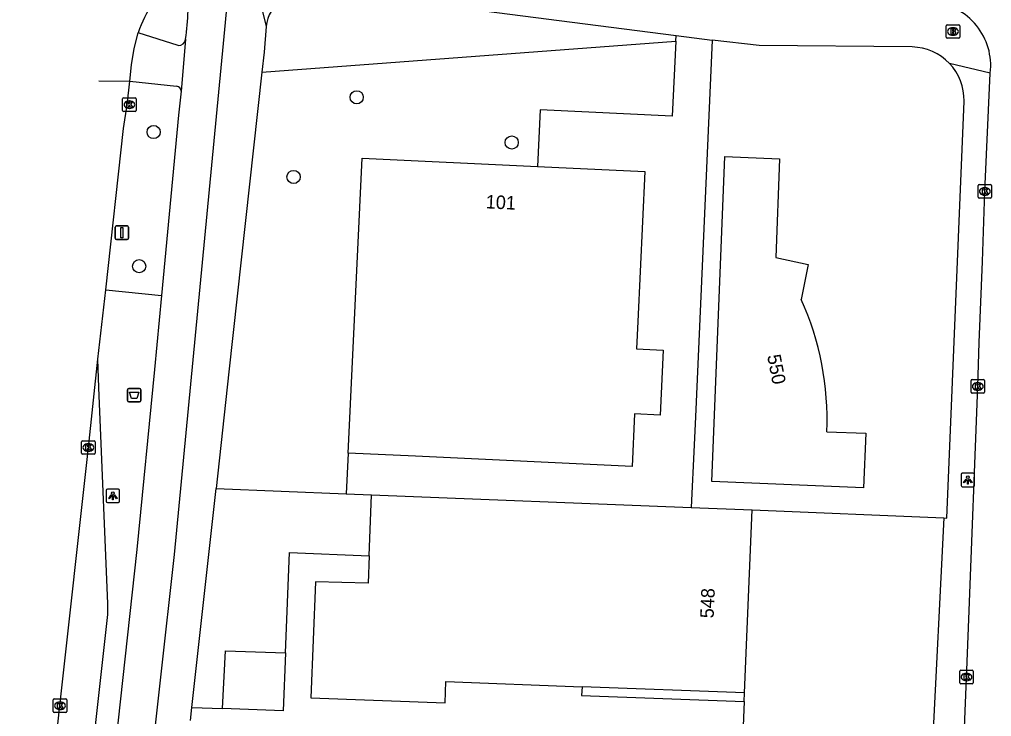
# Model space of a CAD drawing. Extents: x 161355 to 162026, y 386504 to 387459.
# Drawn here: x 161378.2 to 161450.2, y 386765.3 to 386816.9 of the extents above; entities that cross this region are included whole.
import ezdxf

# ---------------------------------------------------------------- set-up
doc = ezdxf.new("R2010")
doc.units = 0
for name, color, linetype in [('IMGEO_Afvalbak', 7, 'Continuous'), ('IMGEO_Boom', 7, 'Continuous'), ('IMGEO_Brandkraan', 7, 'Continuous'), ('IMGEO_Fietspad_gesloten', 7, 'Continuous'), ('IMGEO_Groenvoorziening', 7, 'Continuous'), ('IMGEO_Kolk', 7, 'Continuous'), ('IMGEO_Lichtpunt', 7, 'Continuous'), ('IMGEO_Pand', 7, 'Continuous'), ('IMGEO_Pand_nummerreeks', 7, 'Continuous'), ('IMGEO_Parkeervlak_open', 7, 'Continuous'), ('IMGEO_Rijbaan_lokaal_gesloten', 7, 'Continuous'), ('IMGEO_Rijbaan_lokaal_open', 7, 'Continuous'), ('IMGEO_Verkeersbordpaal', 7, 'Continuous'), ('IMGEO_Voetpad_open', 7, 'Continuous')]:
    doc.layers.add(name, color=color, linetype=linetype)

msp = doc.modelspace()

# ---------------------------------------------------------------- linework, layer by layer
at = {"layer": 'IMGEO_Afvalbak'}
for p, q in [((161386.165, 386788.673), (161386.165, 386789.473)), ((161386.165, 386789.473), (161386.165, 386788.673)), ((161386.265, 386789.573), (161387.055, 386789.573)), ((161387.055, 386789.573), (161386.265, 386789.573)), ((161387.155, 386789.473), (161387.155, 386788.673)), ((161387.155, 386788.673), (161387.155, 386789.473)), ((161387.055, 386788.573), (161386.265, 386788.573)), ((161386.265, 386788.573), (161387.055, 386788.573))]:
    msp.add_line(p, q, dxfattribs=at)
msp.add_lwpolyline([(161386.308, 386789.287), (161387.012, 386789.287), (161386.863, 386788.817), (161386.457, 386788.817), (161386.308, 386789.287)], dxfattribs=at)
for centre, start, end in [((161386.265, 386789.473), 90, 180), ((161386.265, 386789.473), 90, 180), ((161387.055, 386789.473), 0, 90), ((161387.055, 386789.473), 360, 90), ((161386.265, 386788.673), 180, 270), ((161386.265, 386788.673), 180, 270), ((161387.055, 386788.673), 270, 0), ((161387.055, 386788.673), 270, 0)]:
    msp.add_arc(centre, 0.1, start, end, dxfattribs=at)
at = {"layer": 'IMGEO_Boom'}
for centre in [(161403.147, 386811.141), (161388.097, 386808.566), (161414.628, 386807.791), (161398.469, 386805.238), (161387.028, 386798.624)]:
    msp.add_circle(centre, 0.489, dxfattribs=at)
at = {"layer": 'IMGEO_Brandkraan'}
for p, q in [((161446.822, 386815.585), (161446.822, 386816.437)), ((161446.897, 386816.511), (161447.749, 386816.511)), ((161447.31, 386816.291), (161447.335, 386816.291)), ((161447.823, 386816.437), (161447.823, 386815.585)), ((161447.749, 386815.511), (161446.897, 386815.511)), ((161447.333, 386815.731), (161447.308, 386815.731))]:
    msp.add_line(p, q, dxfattribs=at)
for points in [[(161446.822, 386815.585), (161446.822, 386816.437)], [(161446.897, 386816.511), (161447.749, 386816.511)], [(161447.17, 386816.211), (161447.17, 386815.811), (161447.383, 386815.811)], [(161447.401, 386816.211), (161447.17, 386816.211)], [(161447.349, 386816.13), (161447.295, 386816.13), (161447.295, 386816.054)], [(161447.295, 386816.054), (161447.348, 386816.054)], [(161447.357, 386815.978), (161447.295, 386815.978), (161447.295, 386815.897)], [(161447.295, 386815.897), (161447.357, 386815.897)], [(161447.823, 386816.437), (161447.823, 386815.585)], [(161447.749, 386815.511), (161446.897, 386815.511)]]:
    msp.add_lwpolyline(points, dxfattribs=at)
for centre, radius, start, end in [((161446.899, 386816.435), 0.0765, 91.55205, 178.44795), ((161446.899, 386816.435), 0.0765, 91.55205, 178.44795), ((161447.35, 386816.092), 0.0379, 267.82845, 90.93552), ((161447.358, 386815.937), 0.0404, 269.87594, 90.50774), ((161447.405, 386816.066), 0.145, 59.4692, 91.53667), ((161447.43, 386816.113), 0.0922, 285.51372, 58.15012), ((161447.435, 386815.921), 0.105, 301.31148, 78.98903), ((161447.747, 386816.435), 0.0765, 1.55205, 88.44795), ((161447.747, 386816.435), 0.0765, 1.55205, 88.44795), ((161446.899, 386815.587), 0.0765, 181.55205, 268.44795), ((161446.899, 386815.587), 0.0765, 181.55205, 268.44795), ((161447.389, 386816.062), 0.251, 268.66757, 293.53466), ((161447.747, 386815.587), 0.0765, 271.55205, 358.44795), ((161447.747, 386815.587), 0.0765, 271.55205, 358.44795)]:
    msp.add_arc(centre, radius, start, end, dxfattribs=at)
for centre, major_axis, ratio, start_param, end_param in [((161447.309, 386816.011), (-0.387, 0.002), 0.722429, 4.712389, 7.853982), ((161447.334, 386816.011), (-0.39, 0.002), 0.717154, 1.570796, 4.712389)]:
    msp.add_ellipse(centre, major_axis=major_axis, ratio=ratio, start_param=start_param, end_param=end_param, dxfattribs=at)
at = {"layer": 'IMGEO_Fietspad_gesloten'}
for points in [[(161381.864, 386712.557), (161383.032, 386721.496), (161385.721, 386742.066), (161386.605, 386750), (161389.646, 386777.28), (161393.272, 386815.123), (161393.6, 386818.527)], [(161390.466, 386815.452), (161390.418, 386814.821), (161390.137, 386811.593)], [(161390.137, 386811.593), (161389.935, 386809.823), (161388.673, 386796.461)]]:
    msp.add_lwpolyline(points, dxfattribs=at)
msp.add_arc((161373.711, 386817.975), 16.944, 351.43496, 5.63796, dxfattribs=at)
at = {"layer": 'IMGEO_Groenvoorziening'}
for points in [[(161396.119, 386813), (161426.794, 386815.303)], [(161392.725, 386782.167), (161402.362, 386781.767)]]:
    msp.add_lwpolyline(points, dxfattribs=at)
at = {"layer": 'IMGEO_Kolk'}
for p, q in [((161385.803, 386810.167), (161385.803, 386811.019)), ((161385.878, 386811.093), (161386.73, 386811.093)), ((161386.291, 386810.873), (161386.316, 386810.873)), ((161386.804, 386811.019), (161386.804, 386810.167)), ((161386.73, 386810.093), (161385.878, 386810.093)), ((161386.314, 386810.313), (161386.289, 386810.313)), ((161449.184, 386803.743), (161449.184, 386804.595)), ((161449.259, 386804.669), (161450.111, 386804.669)), ((161449.672, 386804.449), (161449.697, 386804.449)), ((161450.185, 386804.595), (161450.185, 386803.743)), ((161450.111, 386803.669), (161449.259, 386803.669)), ((161449.695, 386803.889), (161449.67, 386803.889)), ((161448.663, 386789.296), (161448.663, 386790.148)), ((161448.738, 386790.222), (161449.59, 386790.222)), ((161449.151, 386790.002), (161449.176, 386790.002)), ((161449.664, 386790.148), (161449.664, 386789.296)), ((161449.59, 386789.222), (161448.738, 386789.222)), ((161449.174, 386789.442), (161449.149, 386789.442)), ((161382.763, 386784.772), (161382.763, 386785.624)), ((161382.838, 386785.698), (161383.69, 386785.698)), ((161383.764, 386785.624), (161383.764, 386784.772)), ((161383.274, 386784.918), (161383.249, 386784.918)), ((161383.251, 386785.478), (161383.276, 386785.478)), ((161383.69, 386784.698), (161382.838, 386784.698)), ((161447.828, 386767.769), (161447.828, 386768.621)), ((161447.903, 386768.695), (161448.755, 386768.695)), ((161448.316, 386768.475), (161448.341, 386768.475)), ((161448.829, 386768.621), (161448.829, 386767.769)), ((161448.755, 386767.695), (161447.903, 386767.695)), ((161448.339, 386767.915), (161448.314, 386767.915)), ((161380.657, 386765.642), (161380.657, 386766.494)), ((161380.732, 386766.568), (161381.584, 386766.568)), ((161381.145, 386766.348), (161381.17, 386766.348)), ((161381.658, 386766.494), (161381.658, 386765.642)), ((161381.584, 386765.568), (161380.732, 386765.568)), ((161381.168, 386765.788), (161381.143, 386765.788))]:
    msp.add_line(p, q, dxfattribs=at)
for points in [[(161385.803, 386810.167), (161385.803, 386811.019)], [(161385.878, 386811.093), (161386.73, 386811.093)], [(161386.804, 386811.019), (161386.804, 386810.167)], [(161386.73, 386810.093), (161385.878, 386810.093)], [(161386.124, 386810.793), (161386.247, 386810.793), (161386.247, 386810.642), (161386.377, 386810.793), (161386.541, 386810.793), (161386.395, 386810.642), (161386.548, 386810.393), (161386.396, 386810.393), (161386.311, 386810.557), (161386.247, 386810.49), (161386.247, 386810.393), (161386.124, 386810.393), (161386.124, 386810.793)], [(161449.184, 386803.743), (161449.184, 386804.595)], [(161449.259, 386804.669), (161450.111, 386804.669)], [(161449.505, 386804.369), (161449.628, 386804.369), (161449.628, 386804.218), (161449.758, 386804.369), (161449.922, 386804.369), (161449.776, 386804.218), (161449.929, 386803.969), (161449.777, 386803.969), (161449.692, 386804.133), (161449.628, 386804.066), (161449.628, 386803.969), (161449.505, 386803.969), (161449.505, 386804.369)], [(161450.185, 386804.595), (161450.185, 386803.743)], [(161450.111, 386803.669), (161449.259, 386803.669)], [(161448.663, 386789.296), (161448.663, 386790.148)], [(161448.738, 386790.222), (161449.59, 386790.222)], [(161448.984, 386789.922), (161449.107, 386789.922), (161449.107, 386789.771), (161449.237, 386789.922), (161449.401, 386789.922), (161449.255, 386789.771), (161449.408, 386789.522), (161449.256, 386789.522), (161449.171, 386789.686), (161449.107, 386789.619), (161449.107, 386789.522), (161448.984, 386789.522), (161448.984, 386789.922)], [(161449.664, 386790.148), (161449.664, 386789.296)], [(161449.59, 386789.222), (161448.738, 386789.222)], [(161382.763, 386784.772), (161382.763, 386785.624)], [(161382.838, 386785.698), (161383.69, 386785.698)], [(161383.764, 386785.624), (161383.764, 386784.772)], [(161383.084, 386785.398), (161383.207, 386785.398), (161383.207, 386785.247), (161383.337, 386785.398), (161383.501, 386785.398), (161383.355, 386785.247), (161383.508, 386784.998), (161383.356, 386784.998), (161383.271, 386785.162), (161383.207, 386785.095), (161383.207, 386784.998), (161383.084, 386784.998), (161383.084, 386785.398)], [(161383.69, 386784.698), (161382.838, 386784.698)], [(161447.828, 386767.769), (161447.828, 386768.621)], [(161447.903, 386768.695), (161448.755, 386768.695)], [(161448.149, 386768.395), (161448.272, 386768.395), (161448.272, 386768.244), (161448.402, 386768.395), (161448.566, 386768.395), (161448.42, 386768.244), (161448.573, 386767.995), (161448.421, 386767.995), (161448.336, 386768.159), (161448.272, 386768.092), (161448.272, 386767.995), (161448.149, 386767.995), (161448.149, 386768.395)], [(161448.829, 386768.621), (161448.829, 386767.769)], [(161448.755, 386767.695), (161447.903, 386767.695)], [(161380.657, 386765.642), (161380.657, 386766.494)], [(161380.732, 386766.568), (161381.584, 386766.568)], [(161380.978, 386766.268), (161381.101, 386766.268), (161381.101, 386766.117), (161381.231, 386766.268), (161381.395, 386766.268), (161381.249, 386766.117), (161381.402, 386765.868), (161381.25, 386765.868), (161381.165, 386766.032), (161381.101, 386765.965), (161381.101, 386765.868), (161380.978, 386765.868), (161380.978, 386766.268)], [(161381.658, 386766.494), (161381.658, 386765.642)], [(161381.584, 386765.568), (161380.732, 386765.568)]]:
    msp.add_lwpolyline(points, dxfattribs=at)
for centre, start, end in [((161385.88, 386811.017), 91.55205, 178.44795), ((161385.88, 386811.017), 91.55205, 178.44795), ((161386.728, 386811.017), 1.55205, 88.44795), ((161386.728, 386811.017), 1.55205, 88.44795), ((161385.88, 386810.169), 181.55205, 268.44795), ((161385.88, 386810.169), 181.55205, 268.44795), ((161386.728, 386810.169), 271.55205, 358.44795), ((161386.728, 386810.169), 271.55205, 358.44795), ((161449.261, 386804.593), 91.55205, 178.44795), ((161449.261, 386804.593), 91.55205, 178.44795), ((161450.109, 386804.593), 1.55205, 88.44795), ((161450.109, 386804.593), 1.55205, 88.44795), ((161449.261, 386803.745), 181.55205, 268.44795), ((161449.261, 386803.745), 181.55205, 268.44795), ((161450.109, 386803.745), 271.55205, 358.44795), ((161450.109, 386803.745), 271.55205, 358.44795), ((161448.74, 386790.146), 91.55205, 178.44795), ((161448.74, 386790.146), 91.55205, 178.44795), ((161449.588, 386790.146), 1.55205, 88.44795), ((161449.588, 386790.146), 1.55205, 88.44795), ((161448.74, 386789.298), 181.55205, 268.44795), ((161448.74, 386789.298), 181.55205, 268.44795), ((161449.588, 386789.298), 271.55205, 358.44795), ((161449.588, 386789.298), 271.55205, 358.44795), ((161382.84, 386785.622), 91.55205, 178.44795), ((161382.84, 386785.622), 91.55205, 178.44795), ((161383.688, 386785.622), 1.55205, 88.44795), ((161383.688, 386785.622), 1.55205, 88.44795), ((161382.84, 386784.774), 181.55205, 268.44795), ((161382.84, 386784.774), 181.55205, 268.44795), ((161383.688, 386784.774), 271.55205, 358.44795), ((161383.688, 386784.774), 271.55205, 358.44795), ((161447.905, 386768.619), 91.55205, 178.44795), ((161447.905, 386768.619), 91.55205, 178.44795), ((161448.753, 386768.619), 1.55205, 88.44795), ((161448.753, 386768.619), 1.55205, 88.44795), ((161447.905, 386767.771), 181.55205, 268.44795), ((161447.905, 386767.771), 181.55205, 268.44795), ((161448.753, 386767.771), 271.55205, 358.44795), ((161448.753, 386767.771), 271.55205, 358.44795), ((161380.734, 386766.492), 91.55205, 178.44795), ((161380.734, 386766.492), 91.55205, 178.44795), ((161381.582, 386766.492), 1.55205, 88.44795), ((161381.582, 386766.492), 1.55205, 88.44795), ((161380.734, 386765.644), 181.55205, 268.44795), ((161380.734, 386765.644), 181.55205, 268.44795), ((161381.582, 386765.644), 271.55205, 358.44795), ((161381.582, 386765.644), 271.55205, 358.44795)]:
    msp.add_arc(centre, 0.0765, start, end, dxfattribs=at)
for centre, major_axis, ratio, start_param, end_param in [((161386.29, 386810.593), (-0.387, 0.002), 0.722429, 4.712389, 7.853982), ((161386.315, 386810.593), (-0.39, 0.002), 0.717154, 1.570796, 4.712389), ((161449.671, 386804.169), (-0.387, 0.002), 0.722429, 4.712389, 7.853982), ((161449.696, 386804.169), (-0.39, 0.002), 0.717154, 1.570796, 4.712389), ((161449.15, 386789.722), (-0.387, 0.002), 0.722429, 4.712389, 7.853982), ((161449.175, 386789.722), (-0.39, 0.002), 0.717154, 1.570796, 4.712389), ((161383.25, 386785.198), (-0.387, 0.002), 0.722429, 4.712389, 7.853982), ((161383.275, 386785.198), (-0.39, 0.002), 0.717154, 1.570796, 4.712389), ((161448.315, 386768.195), (-0.387, 0.002), 0.722429, 4.712389, 7.853982), ((161448.34, 386768.195), (-0.39, 0.002), 0.717154, 1.570796, 4.712389), ((161381.144, 386766.068), (-0.387, 0.002), 0.722429, 4.712389, 7.853982), ((161381.169, 386766.068), (-0.39, 0.002), 0.717154, 1.570796, 4.712389)]:
    msp.add_ellipse(centre, major_axis=major_axis, ratio=ratio, start_param=start_param, end_param=end_param, dxfattribs=at)
at = {"layer": 'IMGEO_Lichtpunt'}
for p, q in [((161447.926, 386783.196), (161447.926, 386782.389)), ((161447.926, 386783.196), (161447.926, 386782.389)), ((161448.828, 386783.291), (161448.02, 386783.291)), ((161448.828, 386783.291), (161448.02, 386783.291)), ((161448.922, 386782.389), (161448.922, 386783.196)), ((161448.922, 386782.389), (161448.922, 386783.196)), ((161384.582, 386782.023), (161384.582, 386781.216)), ((161384.582, 386782.023), (161384.582, 386781.216)), ((161385.484, 386782.118), (161384.676, 386782.118)), ((161385.484, 386782.118), (161384.676, 386782.118)), ((161385.578, 386781.216), (161385.578, 386782.023)), ((161385.578, 386781.216), (161385.578, 386782.023)), ((161448.02, 386782.295), (161448.828, 386782.295)), ((161448.02, 386782.295), (161448.828, 386782.295)), ((161384.676, 386781.122), (161385.484, 386781.122)), ((161384.676, 386781.122), (161385.484, 386781.122))]:
    msp.add_line(p, q, dxfattribs=at)
for points in [[(161448.3, 386782.86), (161448.339, 386782.832), (161448.151, 386782.57), (161448.113, 386782.597), (161448.3, 386782.86)], [(161448.402, 386782.812), (161448.449, 386782.812), (161448.449, 386782.49), (161448.402, 386782.49), (161448.402, 386782.812)], [(161448.512, 386782.832), (161448.55, 386782.859), (161448.737, 386782.597), (161448.698, 386782.569), (161448.512, 386782.832)], [(161384.956, 386781.687), (161384.995, 386781.659), (161384.807, 386781.397), (161384.769, 386781.424), (161384.956, 386781.687)], [(161385.058, 386781.639), (161385.105, 386781.639), (161385.105, 386781.317), (161385.058, 386781.317), (161385.058, 386781.639)], [(161385.168, 386781.659), (161385.206, 386781.686), (161385.393, 386781.424), (161385.354, 386781.396), (161385.168, 386781.659)]]:
    msp.add_lwpolyline(points, dxfattribs=at)
for centre in [(161448.425, 386782.994), (161385.081, 386781.821)]:
    msp.add_circle(centre, 0.0994, dxfattribs=at)
for centre, start, end in [((161448.02, 386783.196), 90, 180), ((161448.02, 386783.196), 90, 180), ((161448.828, 386783.196), 0, 90), ((161448.828, 386783.196), 0, 90), ((161384.676, 386782.023), 90, 180), ((161384.676, 386782.023), 90, 180), ((161385.484, 386782.023), 0, 90), ((161385.484, 386782.023), 0, 90), ((161448.02, 386782.389), 180, 270), ((161448.02, 386782.389), 180, 270), ((161448.828, 386782.389), 270, 0), ((161448.828, 386782.389), 270, 360), ((161384.676, 386781.216), 180, 270), ((161384.676, 386781.216), 180, 270), ((161385.484, 386781.216), 270, 0), ((161385.484, 386781.216), 270, 360)]:
    msp.add_arc(centre, 0.0946, start, end, dxfattribs=at)
at = {"layer": 'IMGEO_Pand'}
for points in [[(161402.504, 386784.789), (161403.542, 386806.633), (161416.532, 386806.016)], [(161437.988, 386786.363), (161440.872, 386786.253), (161440.703, 386782.217), (161429.467, 386782.668), (161430.424, 386806.747), (161434.47, 386806.586), (161434.204, 386799.261), (161436.608, 386798.765), (161436.084, 386796.17)], [(161416.532, 386806.016), (161424.493, 386805.638), (161423.965, 386794.522), (161423.869, 386792.503), (161425.857, 386792.409), (161425.628, 386787.593), (161423.729, 386787.683), (161423.544, 386783.789), (161407.499, 386784.552), (161402.504, 386784.789)], [(161404.072, 386777.16), (161404.241, 386781.689)], [(161404.241, 386781.689), (161427.921, 386780.759)], [(161427.921, 386780.759), (161432.449, 386780.581)], [(161431.881, 386767.014), (161432.449, 386780.581)], [(161404.072, 386777.16), (161403.996, 386775.14), (161400.1, 386775.238), (161399.751, 386766.654), (161409.697, 386766.272), (161409.747, 386767.862), (161419.859, 386767.475)], [(161431.881, 386767.014), (161419.859, 386767.475)]]:
    msp.add_lwpolyline(points, dxfattribs=at)
msp.add_arc((161416.228, 386787.227), 21.777, 357.72682, 24.24742, dxfattribs=at)
at = {"layer": 'IMGEO_Parkeervlak_open'}
msp.add_lwpolyline([(161432.449, 386780.581), (161446.64, 386779.978)], dxfattribs=at)
at = {"layer": 'IMGEO_Rijbaan_lokaal_gesloten'}
for points in [[(161386.323, 386812.328), (161386.454, 386813.541), (161386.667, 386814.764), (161386.944, 386815.913)], [(161384.035, 386812.351), (161386.323, 386812.328)], [(161384.555, 386796.868), (161385.854, 386808.827), (161386.133, 386810.572), (161386.323, 386812.328)], [(161383.965, 386791.735), (161384.555, 386796.868)], [(161378.155, 386737.741), (161378.23, 386739.745), (161378.323, 386740.247), (161378.943, 386746.009), (161379.384, 386750), (161381.158, 386766.068), (161383.264, 386785.198), (161383.965, 386791.735)], [(161382.198, 386749.997), (161382.813, 386755.747), (161384.696, 386772.838), (161384.708, 386773.606), (161384.043, 386789.635), (161383.965, 386791.735)]]:
    msp.add_lwpolyline(points, dxfattribs=at)
msp.add_arc((161396.22, 386812.667), 9.827, 131.69474, 160.71213, dxfattribs=at)
at = {"layer": 'IMGEO_Rijbaan_lokaal_open'}
for points in [[(161444.737, 386682.723), (161445.57, 386702.409), (161447.104, 386740.028), (161447.533, 386746.883), (161447.642, 386750), (161447.745, 386752.965), (161447.891, 386757.154), (161448.343, 386768.709), (161448.49, 386772.488), (161449.164, 386789.722), (161449.271, 386792.965), (161449.505, 386798.966), (161449.685, 386804.169), (161450.094, 386812.939)], [(161388.673, 386796.461), (161388.16, 386790.973), (161386.855, 386777.635), (161384.227, 386753.709), (161383.76, 386750), (161383.745, 386749.881)], [(161384.555, 386796.868), (161388.673, 386796.461)]]:
    msp.add_lwpolyline(points, dxfattribs=at)
msp.add_arc((161445.409, 386813.48), 4.716, 353.41201, 84.69576, dxfattribs=at)
at = {"layer": 'IMGEO_Verkeersbordpaal'}
for p, q in [((161385.247, 386800.707), (161385.247, 386801.507)), ((161385.247, 386801.507), (161385.247, 386800.707)), ((161385.347, 386801.607), (161386.137, 386801.607)), ((161386.137, 386801.607), (161385.347, 386801.607)), ((161386.237, 386801.507), (161386.237, 386800.707)), ((161386.237, 386800.707), (161386.237, 386801.507)), ((161386.137, 386800.607), (161385.347, 386800.607)), ((161385.347, 386800.607), (161386.137, 386800.607))]:
    msp.add_line(p, q, dxfattribs=at)
msp.add_lwpolyline([(161385.667, 386801.482), (161385.817, 386801.482), (161385.817, 386800.732), (161385.667, 386800.732), (161385.667, 386801.482)], dxfattribs=at)
for centre, start, end in [((161385.347, 386801.507), 90, 180), ((161385.347, 386801.507), 90, 180), ((161386.137, 386801.507), 0, 90), ((161386.137, 386801.507), 360, 90), ((161385.347, 386800.707), 180, 270), ((161385.347, 386800.707), 180, 270), ((161386.137, 386800.707), 270, 0), ((161386.137, 386800.707), 270, 0)]:
    msp.add_arc(centre, 0.1, start, end, dxfattribs=at)
at = {"layer": 'IMGEO_Voetpad_open'}
for points in [[(161395.184, 386821.499), (161396.429, 386816.391)], [(161399.71, 386819.014), (161407.753, 386818.166), (161426.814, 386815.709)], [(161389.914, 386814.97), (161386.944, 386815.913)], [(161396.429, 386816.391), (161396.283, 386814.488), (161396.119, 386813)], [(161426.794, 386815.303), (161426.52, 386809.746), (161416.731, 386810.211), (161416.532, 386806.016)], [(161426.794, 386815.303), (161426.814, 386815.709)], [(161426.814, 386815.709), (161429.479, 386815.366)], [(161429.479, 386815.366), (161428.242, 386787.469), (161428.15, 386785.397), (161427.921, 386780.759)], [(161444.305, 386814.868), (161432.955, 386814.983), (161429.479, 386815.366)], [(161396.119, 386813), (161393.679, 386790.813), (161392.725, 386782.167)], [(161450.094, 386812.939), (161447.06, 386813.654)], [(161386.323, 386812.328), (161389.793, 386811.961)], [(161446.64, 386779.978), (161446.875, 386779.968), (161448.152, 386810.848)], [(161402.504, 386784.789), (161402.362, 386781.767)], [(161390.933, 386765.929), (161392.725, 386782.167)], [(161402.362, 386781.767), (161404.241, 386781.689)], [(161446.64, 386779.978), (161445.775, 386762.809)], [(161397.87, 386769.993), (161398.176, 386777.414), (161404.072, 386777.16)], [(161393.203, 386765.85), (161393.419, 386770.13), (161397.87, 386769.993)], [(161397.87, 386769.993), (161397.692, 386765.691), (161393.203, 386765.85)], [(161419.859, 386767.475), (161419.809, 386766.821), (161431.844, 386766.388)], [(161431.844, 386766.388), (161431.881, 386767.014)], [(161431.844, 386766.388), (161431.741, 386763.351)], [(161390.826, 386764.964), (161390.933, 386765.929)], [(161390.933, 386765.929), (161393.203, 386765.85)]]:
    msp.add_lwpolyline(points, dxfattribs=at)
for centre, radius, start, end in [((161399.424, 386816.008), 3.02, 84.56742, 172.71385), ((161389.915, 386815.526), 0.556, 269.8578, 352.39637), ((161444.217, 386810.934), 3.935, 43.72635, 88.71195), ((161444.22, 386810.933), 3.933, 358.75889, 43.76971), ((161389.773, 386811.597), 0.364, 359.29851, 86.84031)]:
    msp.add_arc(centre, radius, start, end, dxfattribs=at)

# ---------------------------------------------------------------- texts
at = {"layer": 'IMGEO_Pand_nummerreeks'}
for s, rotation, p in [('101', 357.27845, (161412.69, 386802.915)), ('550', 280.98712, (161433.554, 386791.992)), ('548', 87.60525, (161429.59, 386772.529))]:
    msp.add_text(s, height=1, rotation=rotation, dxfattribs=at).set_placement(p)

doc.saveas('drawing.dxf')
